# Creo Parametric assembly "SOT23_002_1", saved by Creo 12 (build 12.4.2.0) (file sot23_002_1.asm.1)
Units: Custom; MM, KILOGRAM, SECS

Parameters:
  PTC_WM_ITERATION = "0"
  PTC_WM_VERSION = "-.0"
  PTC_WM_LIFECYCLE_STATE = "In Work"
  PTC_WM_LIFECYCLE = "MO_CADDocument"
  PTC_WM_CREATED_BY = "Maximilian Roepper (Z0017RMS: MO)"
  PTC_WM_CREATED_ON = "18-Sep-26 11:36:42 AM"
  PTC_WM_MODIFIED_BY = "Maximilian Roepper (Z0017RMS: MO)"
  PTC_WM_MODIFIED_ON = "18-Sep-26 11:36:46 AM"
  PDMLINKNUMBER = "PDM000071454946"
  PTC_WM_NAME = "sot23_002_1.asm"
  PTC_WM_NUMBER = "PDM000071454946"

Other parameters: WEIGHT, WEIGHT_FACTOR, WEIGHT_ADD, MC_ERRORS, SUPPLIER, ISPOSITIONINGASSEMBLY

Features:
  1. coordinate system
  2. imported feature
  3. component "SOT23_LEFT001_1"
  4. component "SOT23_RIGHT001_1"

Other named items: DRW_VIEW_ORG, ROUGH-GROB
